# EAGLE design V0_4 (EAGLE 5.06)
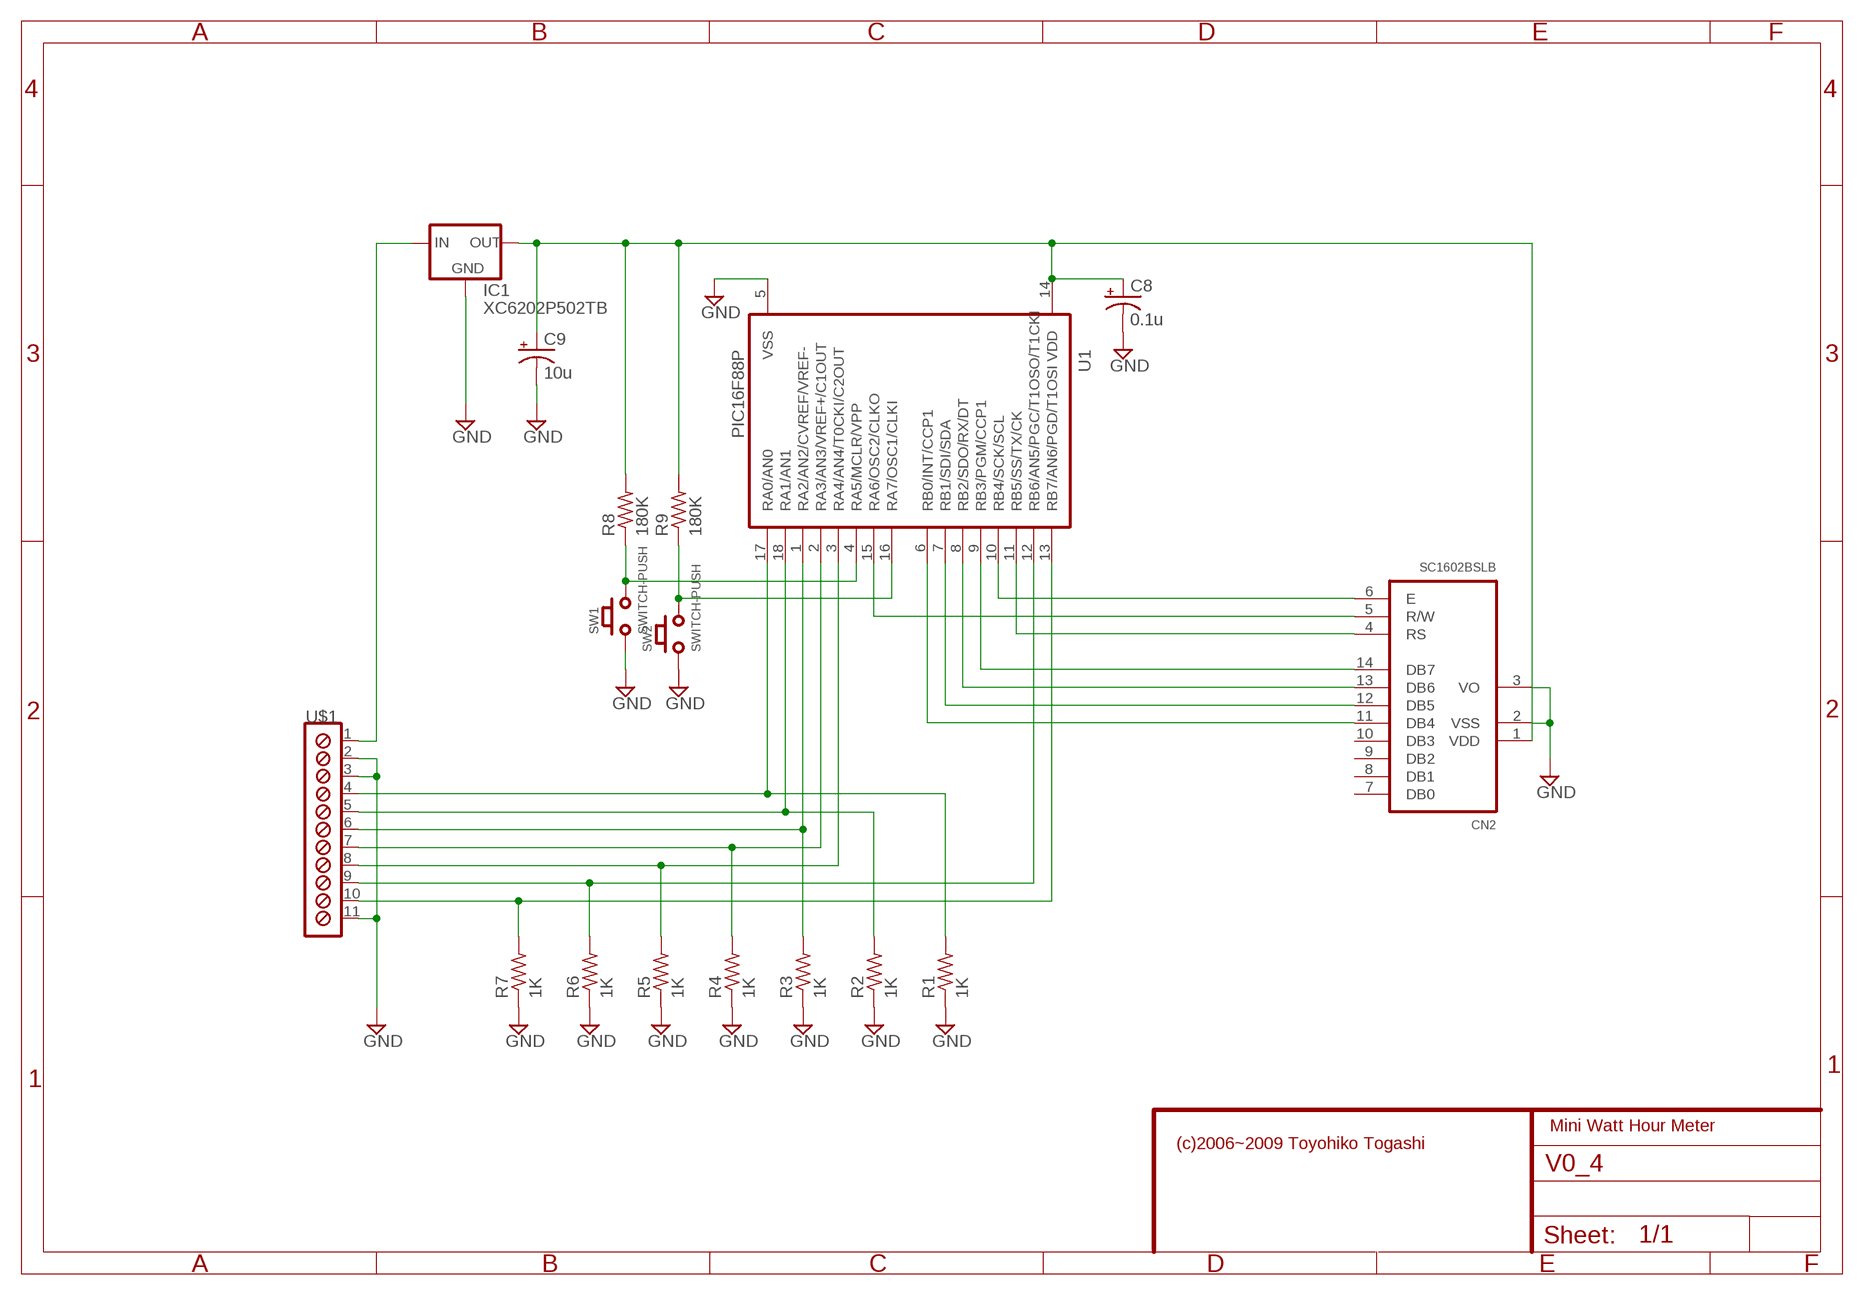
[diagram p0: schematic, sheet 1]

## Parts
C8  0.1u  CPOL-USE2.5-6  [E2,5-6]
C9  10u  CPOL-USE2.5-6  [E2,5-6]
CN2  SC1602BSLB  [MA07-2]
IC1  XC6202P502TB  78LXX  [78LXX]
R1  1K  R-US_0204/7  [0204/7]
R2  1K  R-US_0204/7  [0204/7]
R3  1K  R-US_0204/7  [0204/7]
R4  1K  R-US_0204/7  [0204/7]
R5  1K  R-US_0204/7  [0204/7]
R6  1K  R-US_0204/7  [0204/7]
R7  1K  R-US_0204/7  [0204/7]
R8  180K  R-US_0204/7  [0204/7]
R9  180K  R-US_0204/7  [0204/7]
SW1  SWITCH-PUSH  [SWITCH-PUSH]
SW2  SWITCH-PUSH  [SWITCH-PUSH]
U1  PIC16F88P  [DIL18]
U$1  CONN-SCREW-11P  [CONN-SCREW-11P]

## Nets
CN1: C8.+ C9.+ CN2.1(VDD) IC1.OUT R8.2 R9.2 U1.14(VDD)
GND: C8.- C9.- CN2.2(VSS) CN2.3(VO) IC1.GND R1.1 R2.1 R3.1 R4.1 R5.1 R6.1 R7.1 SW1.P$1(A1) SW2.P$1(A1) U1.5(VSS) U$1.2 U$1.3 U$1.11
N$1: R3.2 U1.1(RA2/AN2/CVREF/VREF-) U$1.6
N$2: IC1.IN U$1.1
N$3: R2.2 U1.18(RA1/AN1) U$1.5
N$4: R1.2 U1.17(RA0/AN0) U$1.4
N$6: R4.2 U1.2(RA3/AN3/VREF+/C1OUT) U$1.7
N$12: R5.2 U1.3(RA4/AN4/T0CKI/C2OUT) U$1.8
N$13: R6.2 U1.12(RB6/AN5/PGC/T1OSO/T1CKI) U$1.9
N$14: R7.2 U1.13(RB7/AN6/PGD/T1OSI) U$1.10
N$15: CN2.11(DB4) U1.6(RB0/INT/CCP1)
N$16: CN2.12(DB5) U1.7(RB1/SDI/SDA)
N$17: CN2.13(DB6) U1.8(RB2/SDO/RX/DT)
N$18: CN2.14(DB7) U1.9(RB3/PGM/CCP1)
N$19: CN2.4(RS) U1.11(RB5/SS/TX/CK)
N$20: CN2.5(R/W) U1.15(RA6/OSC2/CLKO)
N$21: CN2.6(E) U1.10(RB4/SCK/SCL)
N$23: R8.1 SW1.P$2(A2) U1.4(RA5/MCLR/VPP)
N$24: R9.1 SW2.P$2(A2) U1.16(RA7/OSC1/CLKI)
Unconnected: CN2.7(DB0) CN2.8(DB1) CN2.9(DB2) CN2.10(DB3)

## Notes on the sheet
- Mini Watt Hour Meter
- (c)2006~2009 Toyohiko Togashi

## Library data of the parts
C8 C9 = rcl:CPOL-US: POLARIZED CAPACITOR, American symbol
CN2 = TOG:SC1602BSLB
IC1 = v-reg:78LXX: VOLTAGE REGULATOR
R1-R9 = rcl:R-US_: RESISTOR, American symbol
SW1 SW2 = TOG:SWITCH-PUSH
U1 = microchip:PIC16F88
U$1 = TOG:CONN-SCREW-11P

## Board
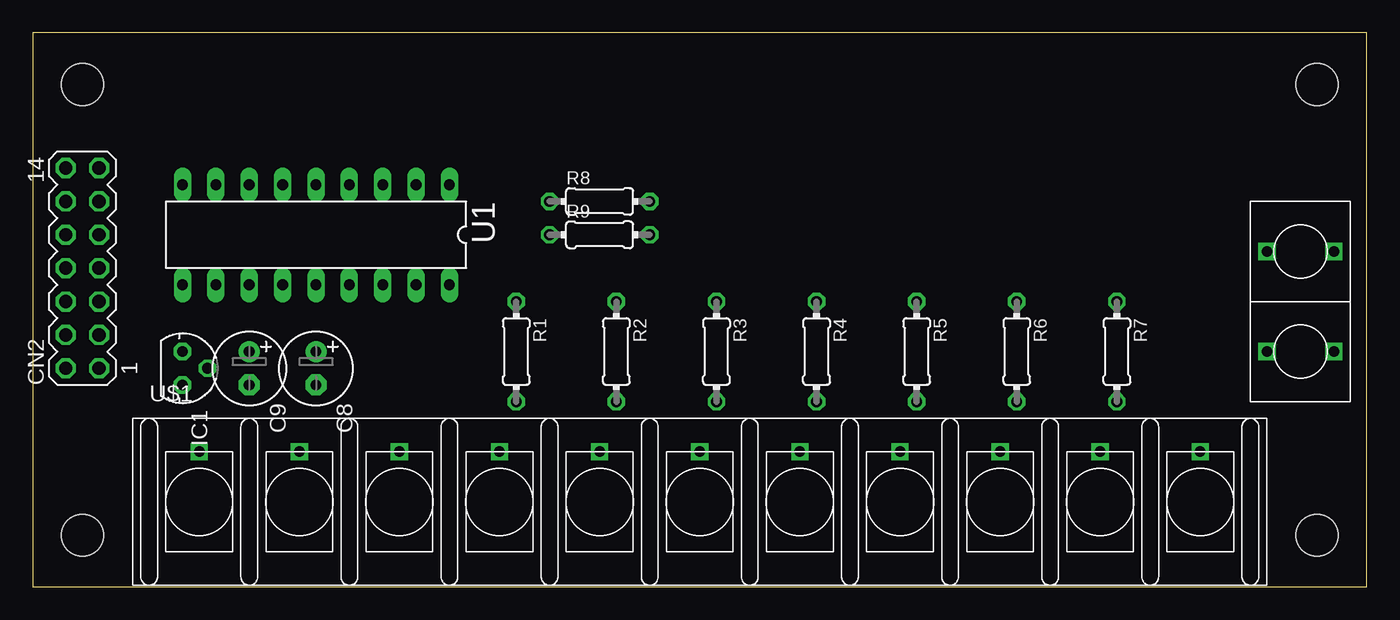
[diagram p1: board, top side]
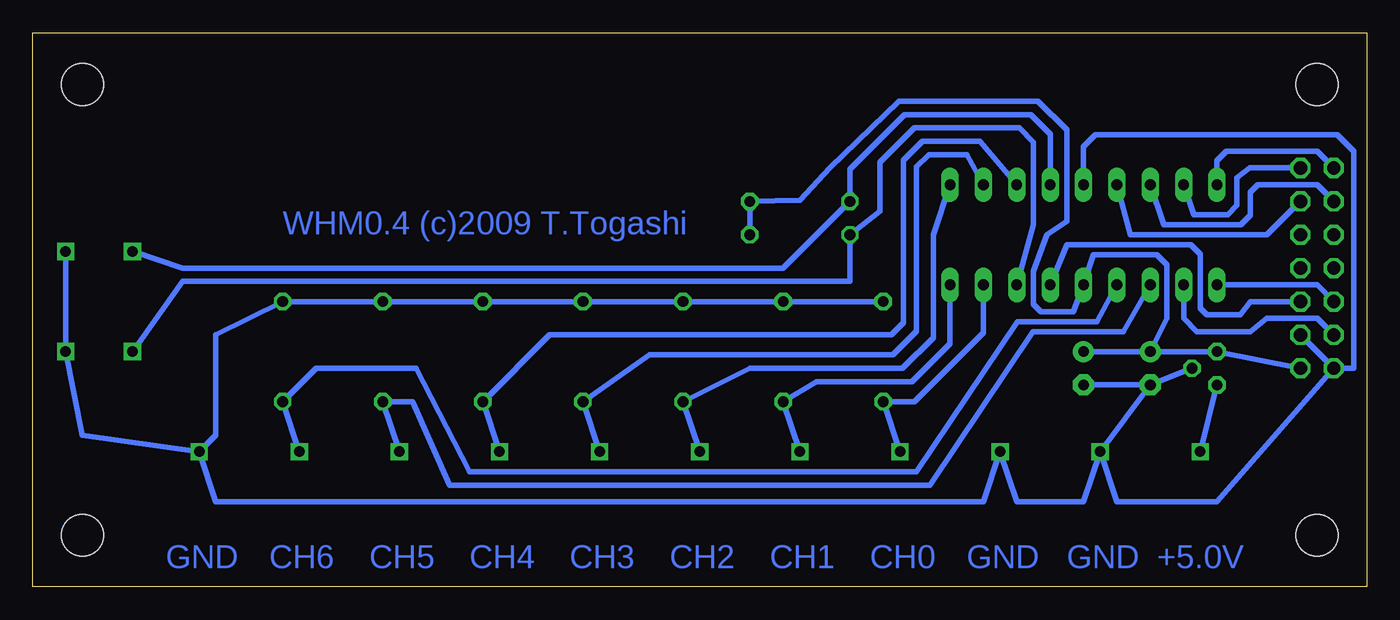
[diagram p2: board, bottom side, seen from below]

Size 101.52 x 42.15 mm. Coordinates in mm from the lower left corner, seen from the top.
Outline: 0,0 101.52,0 101.52,42.15 0,42.15 0,0
Copper layers (1*16): Top 0.035mm / dielectric 1.5mm / Bottom 0.035mm
Design rules "default": minimum track width 10mil, minimum drill 24mil, track to track 8mil, track to pad 8mil, pad to pad 8mil, via to via 8mil, smd to smd 8mil, copper to edge 40mil, drill to drill 8mil, minimum pad ring 10mil, minimum via ring 8mil, stop-mask expansion 4mil, vias tented up to drill 0mil, thermal gap 10mil
Holes 3.2 mm at 3.77,3.93 97.75,3.93 97.75,38.22 3.77,38.22

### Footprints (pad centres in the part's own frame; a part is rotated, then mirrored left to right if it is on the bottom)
E2,5-6 = drill 0.813 pad 1.6 round: + -1.27,0 | drill 0.813 pad 1.6 octagon: - 1.27,0
MA07-2 = drill 1.016 octagon: 1 -7.62,-1.27; 2 -7.62,1.27; 3 -5.08,-1.27; 4 -5.08,1.27; 5 -2.54,-1.27; 6 -2.54,1.27; 7 0,-1.27; 8 0,1.27; 9 2.54,-1.27; 10 2.54,1.27; 11 5.08,-1.27; 12 5.08,1.27; 13 7.62,-1.27; 14 7.62,1.27
78LXX = drill 0.813 octagon: GND 0,1.905; IN 1.27,0; OUT -1.27,0
0204/7 = drill 0.813 octagon: 1 -3.81,0; 2 3.81,0
SWITCH-PUSH = drill 0.8 square: P$1 0,2.54; P$2 0,-2.54
DIL18 = drill 0.813 long: 1 -10.16,-3.81; 2 -7.62,-3.81; 3 -5.08,-3.81; 4 -2.54,-3.81; 5 0,-3.81; 6 2.54,-3.81; 7 5.08,-3.81; 8 7.62,-3.81; 9 10.16,-3.81; 10 10.16,3.81; 11 7.62,3.81; 12 5.08,3.81; 13 2.54,3.81; 14 0,3.81; 15 -2.54,3.81; 16 -5.08,3.81; 17 -7.62,3.81; 18 -10.16,3.81
CONN-SCREW-11P = drill 0.8 square: 1 -38.1,3.81; 2 -30.48,3.81; 3 -22.86,3.81; 4 -15.24,3.81; 5 -7.62,3.81; 6 0,3.81; 7 7.62,3.81; 8 15.24,3.81; 9 22.86,3.81; 10 30.48,3.81; 11 38.1,3.81

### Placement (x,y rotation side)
C8  21.55,16.63 270 top
C9  16.47,16.63 270 top
CN2  3.77,24.25 90 top
IC1  11.39,16.63 270 top
R1  36.79,17.9 270 top
R2  44.41,17.9 270 top
R3  52.03,17.9 270 top
R4  59.65,17.9 270 top
R5  67.27,17.9 270 top
R6  74.89,17.9 270 top
R7  82.51,17.9 270 top
R8  43.14,29.33 0 top
R9  43.14,26.79 0 top
SW1  96.48,25.52 270 top
SW2  96.48,17.9 270 top
U1  21.55,26.79 180 top
U$1  50.76,6.47 0 top

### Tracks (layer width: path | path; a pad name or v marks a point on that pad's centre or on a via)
CN1
  Bottom 0.406: CN2.1 IC1.OUT C9.+ | C9.+ 15.2,20.44 15.2,24.51 15.96,25.27 20.79,25.27 U1.14 22.31,20.95 24.79,20.95 25.36,21.52 25.36,24 24.35,26.79 22.82,27.81 22.82,34.77 25.01,36.95 35.62,36.95 40.86,31.87 43.14,29.43 R8.2 R9.2 | C9.+ C8.+
GND
  Bottom 0.406: U$1.2 21.55,6.47 26.63,6.47 U$1.3 29.17,6.47 87.59,6.47 U$1.11 | U$1.11 97.75,11.55 SW2.P$1 SW1.P$1 | U$1.2 19.01,6.47 11.39,6.47 CN2.2 | U$1.2 C9.- | C9.- C8.- | R1.1 R2.1 R3.1 R4.1 R5.1 R6.1 R7.1 87.59,19.17 87.59,11.55 U$1.11 | C9.- IC1.GND | CN2.2 CN2.3 | U1.5 21.55,33.5 20.64,34.41 2.25,34.41 0.98,33.14 0.98,16.63 CN2.2
N$1
  Bottom 0.406: U$1.6 R3.2 46.95,16.63 35.32,16.63 32.98,18.97 32.98,26.79 U1.1
N$2
  Bottom 0.406: U$1.1 IC1.IN
N$3
  Bottom 0.406: U$1.5 R2.2 41.87,15.62 34.61,15.62 31.71,18.51 U1.18
N$4
  Bottom 0.406: U$1.4 R1.2 34.41,14.09 29.17,19.33 U1.17
N$6
  Bottom 0.406: U$1.7 R4.2 54.57,17.65 36.05,17.65 34.25,19.44 34.25,31.97 33.34,32.89 30.44,32.89 U1.2
N$12
  Bottom 0.406: U$1.8 R5.2 62.19,19.17 36.18,19.17 35.27,20.09 35.27,32.47 33.83,33.9 29.43,33.9 U1.3
N$13
  Bottom 0.406: U$1.9 R6.2 72.61,14.09 69.81,7.74 33.24,7.74 25.41,19.43 18.5,19.43 U1.12
N$14
  Bottom 0.406: U$1.10 R7.2 79.97,16.63 72.35,16.63 68.29,8.76 34.25,8.76 26.58,20.19 20.54,20.19 U1.13
N$15
  Bottom 0.406: CN2.11 7.58,26.79 18,26.79 U1.6
N$16
  Bottom 0.406: CN2.12 3.77,30.6 8.28,30.6 8.85,30.03 8.85,28.27 9.57,27.55 15.46,27.55 U1.7
N$17
  Bottom 0.406: U1.8 13.17,28.32 10.59,28.32 9.87,29.03 9.87,31.14 8.88,31.9 CN2.13
N$18
  Bottom 0.406: U1.9 11.39,32.42 10.67,33.14 3.77,33.14 CN2.14
N$19
  Bottom 0.406: U1.11 13.93,20.44 12.92,19.43 8.85,19.43 7.58,20.44 3.77,20.44 CN2.4
N$20
  Bottom 0.406: CN2.5 8.85,21.71 9.61,20.7 12.15,20.7 12.66,21.2 12.66,25.31 13.38,26.03 22.82,26.03 U1.15
N$21
  Bottom 0.406: U1.10 3.77,22.98 CN2.6
N$23
  Bottom 0.406: U1.4 24.09,34.45 25.57,35.94 35.17,35.94 39.33,31.77 R8.1 44.41,24.25 90.13,24.25 SW1.P$2
N$24
  Bottom 0.406: U1.16 25.36,27.55 25.36,33.84 26.44,34.92 34.43,34.92 37.05,32.3 37.05,28.57 R9.1 39.33,23.24 90.13,23.24 SW2.P$2

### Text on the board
Bottom: WHM0.4 (c)2009 T.Togashi | +5.0V | GND | GND | CH0 | CH1 | CH2 | CH3 | CH4 | CH5 | CH6 | GND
